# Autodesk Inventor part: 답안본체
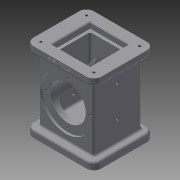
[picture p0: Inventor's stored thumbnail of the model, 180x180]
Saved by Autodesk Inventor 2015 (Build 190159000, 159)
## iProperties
Created: 2017-08
Part Number: 답안본체
Material: 일반
Document SubType Name: Modeling
Designer: Administrator
Density: 1 g/cm^3
Appearance: 기본값
Author: Administrator
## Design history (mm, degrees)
sketch "스케치1"
  geometry: L1 (-46, 41)-(46, 41); L2 (46, 41)-(46, -41); L3 (46, -41)-(-46, -41); L4 (-46, -41)-(-46, 41); L5 (-46, 41)-(46, -41); 2 further points
  constraints: 10 end point, 2 parallel, 1 coincident, 1 horizontal, 1 midpoint, 1 perpendicular
  dimensions: "d0" = 92 distance of L1.start L1.end; "d1" = 82 distance of L3.end L1.start
extrude "돌출1" new body sketch "스케치1" distance "d2" = 10; taper "d3" = 0 deg
sketch "스케치2"
  geometry: L1 (-37, 33)-(37, 33); L2 (37, 33)-(37, -33); L3 (37, -33)-(-37, -33); L4 (-37, -33)-(-37, 33); L5 (-37, 33)-(37, -33); 2 further points
  constraints: 10 end point, 2 parallel, 1 coincident, 1 horizontal, 1 midpoint, 1 perpendicular
  dimensions: "d4" = 74 distance of L1.start L1.end; "d5" = 66 distance of L3.end L1.start
extrude "돌출2" join sketch "스케치2" distance "d6" = 88; taper "d7" = 0 deg
sketch "스케치3"
  geometry: L1 (37, 33)-(37, -33) reference; L2 (37, -33)-(-37, -33) reference; L3 (-37, -33)-(-37, 33) reference; L4 (-37, 33)-(37, 33) reference; L5 (46, 41)-(-46, 41) reference; L6 (-46, 41)-(-46, -41) reference; L7 (-46, -41)-(46, -41) reference; L8 (46, -41)-(46, 41) reference; L9 (-46, 41)-(46, 41); L10 (46, 41)-(46, -41); L11 (46, -41)-(-46, -41); L12 (-46, -41)-(-46, 41); 1 further point
  constraints: 8 end point, 2 parallel, 1 horizontal, 1 perpendicular
extrude "돌출3" join sketch "스케치3" distance "d8" = 10; taper "d9" = 0 deg
sketch "스케치4"
  geometry: L1 (24, -24)-(-24, -24); L2 (-24, -24)-(-24, 24); L3 (-24, 24)-(24, 24); L4 (24, 24)-(24, -24); L5 (24, -24)-(-24, 24); 2 further points
  constraints: 10 end point, 2 parallel, 1 coincident, 1 horizontal, 1 midpoint, 1 perpendicular
  dimensions: "d10" = 48 distance of L1.start L1.end; "d11" = 48 distance of L3.end L1.start
extrude "돌출4" cut sketch "스케치4" distance "d12" = 16; taper "d13" = 0 deg
sketch "스케치6"
  geometry: L1 (-26, 26)-(26, 26); L2 (26, 26)-(26, -26); L3 (26, -26)-(-26, -26); L4 (-26, -26)-(-26, 26); L5 (-26, 26)-(26, -26); 2 further points
  constraints: 10 end point, 2 parallel, 1 coincident, 1 horizontal, 1 midpoint, 1 perpendicular
  dimensions: "d18" = 52 distance of L1.start L1.end; "d19" = 52 distance of L3.end L1.start
extrude "돌출6" cut sketch "스케치6" distance "d20" = 8; taper "d21" = 0 deg
sketch "스케치7" dims "d71" = 3
  geometry: L1 (-22, 22)-(22, 22); L2 (22, 22)-(22, -22); L3 (22, -22)-(-22, -22); L4 (-22, -22)-(-22, 22); L5 (-22, 22)-(22, -22); 2 further points
  constraints: 10 end point, 2 parallel, 1 coincident, 1 horizontal, 1 midpoint, 1 perpendicular
  dimensions: "d22" = 44 distance of L1.start L1.end; "d23" = 44 distance of L3.end L1.start
extrude "돌출7" cut sketch "스케치7" distance "d24" = 74; taper "d25" = 0 deg
sketch "스케치8"
  geometry: L1 (11, 98)-(63, 98) reference; L2 (37, 98)-(37, -10); L3 (83, -10)-(-9, -10) reference; C1 r 35 at (37, 44)
  constraints: 2 end point, 2 midpoint, 1 centre point, 1 vertical
  dimensions: "d26" = 70 diameter of C1; "d27" = 54 distance from line of L3 C1.centre
extrude "돌출8" cut sketch "스케치8" distance "d28" = 3; taper "d29" = 0 deg
sketch "스케치10"
  geometry: C1 r 35 at (0, 0) reference; C2 r 24 at (0, 0); 1 further point
  constraints: 1 centre point, 1 coincident
  dimensions: "d30" = 48 diameter of C2
extrude "돌출9" cut sketch "스케치10" stored distance "d31" = 3; taper "d32" = 0 deg
sketch "스케치11"
  geometry: L1 (0, 0)-(0, -29); C1 r 24 at (0, 0) reference; C2 r 35 at (0, 0) reference; 2 further points
  constraints: 2 end point, 1 coincident, 1 vertical
  dimensions: "d33" = 29 distance of L1.start L1.end
hole "구멍1" sketch "스케치11" at (0, -29) diameter "d34" = 3.242; stored, may be unused: countersink angle "d38" = 90 deg, drill point angle "d40" = 118 deg; dims "d35" = 4, "d36" = 4, "d37" = 2, "d39" = 6
fillet "모깎기1" dims "d44" = 10
fillet "모깎기2" dims "d45" = 10
sketch "스케치12"
  geometry: L1 (-46, 31)-(-46, -31) reference; L2 (-36, -41)-(36, -41) reference; L3 (46, -31)-(46, 31) reference; L4 (36, 41)-(-36, 41) reference; L5 (-26, -26)-(-26, 26) reference; L6 (-26, 26)-(26, 26) reference; L7 (26, 26)-(26, -26) reference; L8 (26, -26)-(-26, -26) reference; A1 r 10 centre (-36, 31) between (-36, 41) and (-46, 31) reference; A2 r 10 centre (-36, -31) between (-46, -31) and (-36, -41) reference; A3 r 10 centre (36, -31) between (36, -41) and (46, -31) reference; A4 r 10 centre (36, 31) between (46, 31) and (36, 41) reference; 5 further points
  constraints: 4 coincident
hole "구멍2" sketch "스케치12" at (-36, 31), (36, 31), (36, -31), (-36, -31) diameter "d46" = 3.242; stored, may be unused: countersink angle "d50" = 90 deg, drill point angle "d52" = 118 deg; dims "d47" = 4, "d48" = 4, "d49" = 2, "d51" = 6
sketch "스케치13"
  geometry: L1 (24, 24)-(24, -24) reference; L2 (24, -24)-(-24, -24) reference; L3 (-24, -24)-(-24, 24) reference; L4 (-24, 24)-(24, 24) reference; L5 (36, 41)-(-36, 41) reference; L6 (-46, 31)-(-46, -31) reference; L7 (-36, -41)-(36, -41) reference; L8 (46, -31)-(46, 31) reference; C1 r 1.621 at (36, -31) reference; C2 r 1.621 at (-36, -31) reference; C3 r 1.621 at (-36, 31) reference; C4 r 1.621 at (36, 31) reference; A1 r 10 centre (36, 31) between (46, 31) and (36, 41) reference; A2 r 10 centre (-36, 31) between (-36, 41) and (-46, 31) reference; A3 r 10 centre (-36, -31) between (-46, -31) and (-36, -41) reference; A4 r 10 centre (36, -31) between (36, -41) and (46, -31) reference; 5 further points
  constraints: 4 coincident
hole "구멍3" sketch "스케치13" at (36, -31), (-36, -31), (-36, 31), (36, 31) diameter "d53" = 3.242; stored, may be unused: countersink angle "d57" = 90 deg, drill point angle "d59" = 118 deg; dims "d54" = 4, "d55" = 4, "d56" = 2, "d58" = 6
sketch "스케치14"
  geometry: L1 (-98, 64)-(-98, 2) reference; L2 (-98, 33)-(10, 33); L3 (10, 64)-(10, 2) reference; 2 further points
  constraints: 2 end point, 2 point on line, 1 horizontal, 1 midpoint
  dimensions: "d60" = 38 distance from line of point (-28, 33) L3; "d61" = 42 distance of point (-70, 33) point (-28, 33)
hole "구멍4" sketch "스케치14" at (-28, 33), (-70, 33) diameter "d62" = 4.134; stored, may be unused: countersink angle "d66" = 90 deg, drill point angle "d68" = 118 deg; dims "d63" = 100, "d64" = 4, "d65" = 2, "d67" = 6
fillet "모깎기3" dims "d69" = 3
fillet "모깎기4" dims "d70" = 3
fillet "모깎기5" dims "d71" = 3
fillet "모깎기6" dims "d72" = 3
sketch "스케치16"
  geometry: L1 (13.757, 6.644)-(58.243, 6.644); L2 (58.243, 6.644)-(58.243, -14.644); L3 (58.243, -14.644)-(13.757, -14.644); L4 (13.757, -14.644)-(13.757, 6.644); L5 (13.757, -14.644)-(58.243, 6.644); L6 (-10, 0)-(-10, -7) reference; L7 (36, -14.644)-(36, 6.644); L8 (13.757, -4)-(58.243, -4); L9 (0, 0)-(72, 0) reference; 1 further point
  constraints: 6 end point, 4 midpoint, 2 other
  dimensions: "d73" = 46 distance between parallel lines of L6 L7; "d74" = 4 distance between parallel lines of L8 L9
feature "엠보싱1" sketch "스케치16" dims "d0" = 92, "d1" = 82, "d75" = 0.5, "d76" = 0
chamfer "모따기1" distance "d77" = 1; stored, may be unused: second distance "d78" = 2, angle "d79" = 45 deg
chamfer "모따기2" distance "d80" = 1; stored, may be unused: second distance "d81" = 2, angle "d82" = 45 deg
fillet "모깎기7" dims "d83" = 3
fillet "모깎기8" dims "d84" = 3
node "솔리드1"
mirror "대칭1"
pattern_circular "원형 패턴1" dims angle "d42" = 360 deg
mirror "대칭2"
node "투영된 루프1"
node "투영된 루프2"
node "투영된 루프3"
node "투영된 루프4"
node "투영된 루프5"
